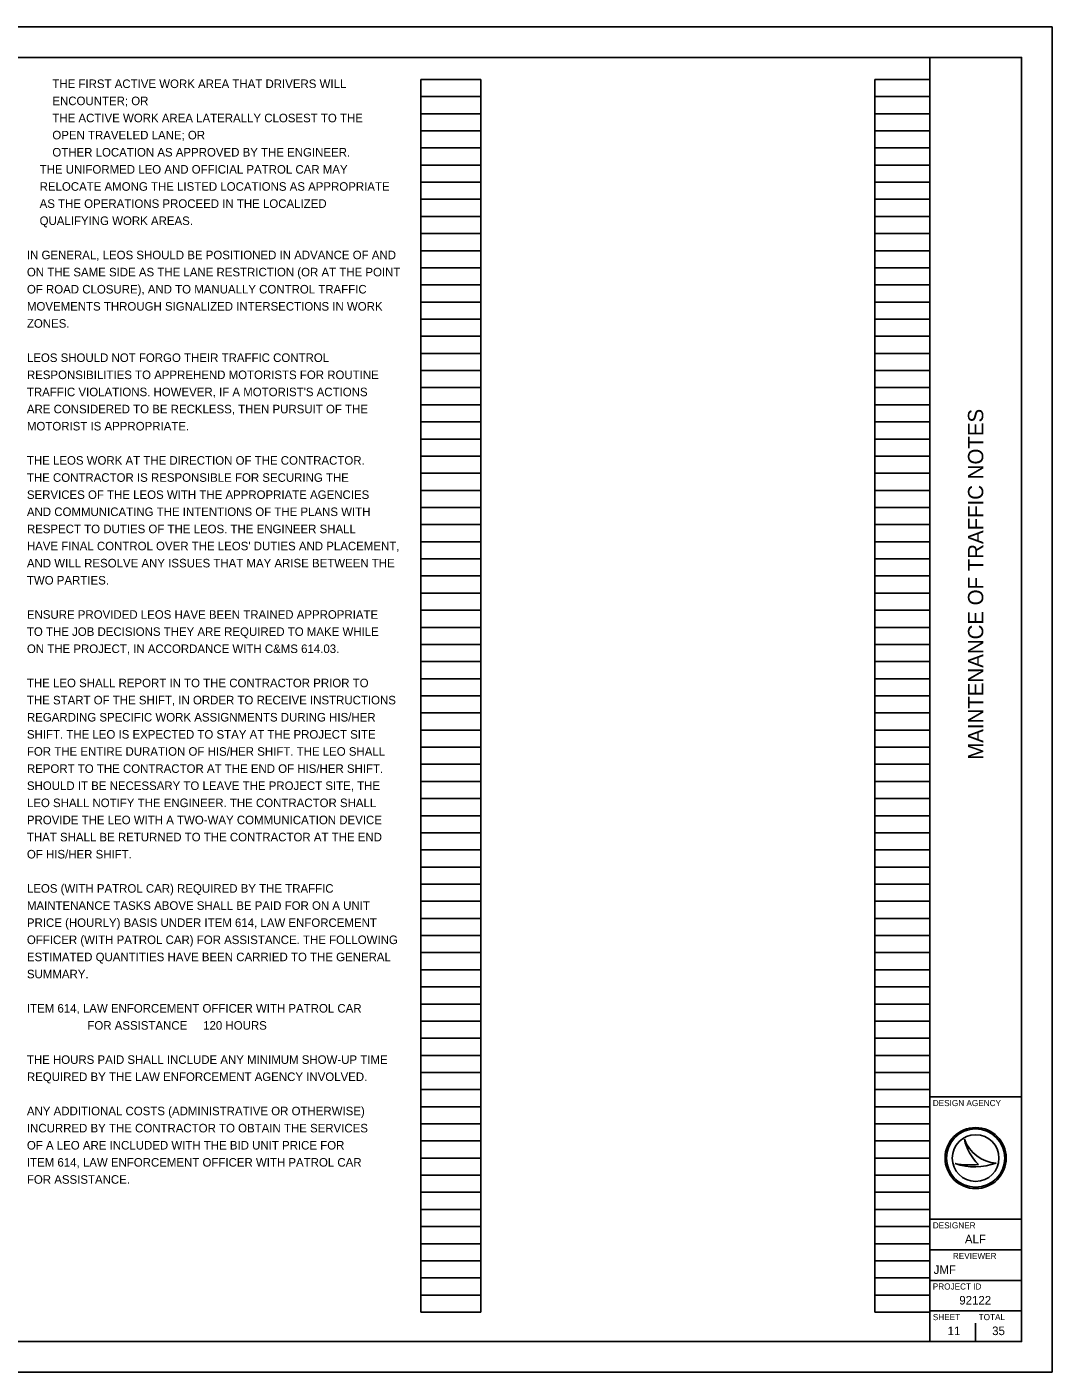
# Model space of a CAD drawing. Extents: x 0 to 34, y 0 to 22.
# Drawn here: x 17.24 to 34, y 0 to 22 of the extents above; entities that cross this region are included whole.
import ezdxf

# ---------------------------------------------------------------- set-up
doc = ezdxf.new("R2010")
doc.units = 0
for name, color, linetype in [('SH_Border', 7, 'Continuous'), ('SH_Cut_Line', 7, 'Continuous'), ('SH_Data', 7, 'Continuous'), ('SH_Text', 7, 'Continuous')]:
    doc.layers.add(name, color=color, linetype=linetype)

msp = doc.modelspace()

# ---------------------------------------------------------------- linework, layer by layer
at = {"layer": 'SH_Border'}
for p, q in [((32, 0.5), (32, 21.5)), ((32, 4.5), (33.5, 4.5)), ((32, 2.5), (33.5, 2.5)), ((32, 2), (33.5, 2)), ((32, 1.5), (33.5, 1.5)), ((32, 1), (33.5, 1))]:
    msp.add_line(p, q, dxfattribs=at)
msp.add_lwpolyline([(1.5, 21.5), (33.5, 21.5), (33.5, 0.5), (1.5, 0.5)], close=True, dxfattribs=at)
at = {"layer": 'SH_Cut_Line'}
msp.add_lwpolyline([(0, 0), (34, 0), (34, 22), (0, 22)], close=True, dxfattribs=at)
at = {"layer": 'SH_Data'}
for p, q in [((23.68, 0.98), (23.68, 21.14)), ((23.68, 21.14), (24.66, 21.14)), ((24.66, 0.98), (24.66, 21.14)), ((31.1, 0.98), (31.1, 21.14)), ((31.1, 21.14), (32, 21.14)), ((32, 0.98), (32, 21.14)), ((23.68, 20.86), (24.66, 20.86)), ((31.1, 20.86), (32, 20.86)), ((23.68, 20.58), (24.66, 20.58)), ((31.1, 20.58), (32, 20.58)), ((23.68, 20.3), (24.66, 20.3)), ((31.1, 20.3), (32, 20.3)), ((23.68, 20.02), (24.66, 20.02)), ((31.1, 20.02), (32, 20.02)), ((23.68, 19.74), (24.66, 19.74)), ((31.1, 19.74), (32, 19.74)), ((23.68, 19.46), (24.66, 19.46)), ((31.1, 19.46), (32, 19.46)), ((23.68, 19.18), (24.66, 19.18)), ((31.1, 19.18), (32, 19.18)), ((23.68, 18.9), (24.66, 18.9)), ((31.1, 18.9), (32, 18.9)), ((23.68, 18.62), (24.66, 18.62)), ((31.1, 18.62), (32, 18.62)), ((23.68, 18.34), (24.66, 18.34)), ((31.1, 18.34), (32, 18.34)), ((23.68, 18.06), (24.66, 18.06)), ((31.1, 18.06), (32, 18.06)), ((23.68, 17.78), (24.66, 17.78)), ((31.1, 17.78), (32, 17.78)), ((23.68, 17.5), (24.66, 17.5)), ((31.1, 17.5), (32, 17.5)), ((23.68, 17.22), (24.66, 17.22)), ((31.1, 17.22), (32, 17.22)), ((23.68, 16.94), (24.66, 16.94)), ((31.1, 16.94), (32, 16.94)), ((23.68, 16.66), (24.66, 16.66)), ((31.1, 16.66), (32, 16.66)), ((23.68, 16.38), (24.66, 16.38)), ((31.1, 16.38), (32, 16.38)), ((23.68, 16.1), (24.66, 16.1)), ((31.1, 16.1), (32, 16.1)), ((23.68, 15.82), (24.66, 15.82)), ((31.1, 15.82), (32, 15.82)), ((23.68, 15.54), (24.66, 15.54)), ((31.1, 15.54), (32, 15.54)), ((23.68, 15.26), (24.66, 15.26)), ((31.1, 15.26), (32, 15.26)), ((23.68, 14.98), (24.66, 14.98)), ((31.1, 14.98), (32, 14.98)), ((23.68, 14.7), (24.66, 14.7)), ((31.1, 14.7), (32, 14.7)), ((23.68, 14.42), (24.66, 14.42)), ((31.1, 14.42), (32, 14.42)), ((23.68, 14.14), (24.66, 14.14)), ((31.1, 14.14), (32, 14.14)), ((23.68, 13.86), (24.66, 13.86)), ((31.1, 13.86), (32, 13.86)), ((23.68, 13.58), (24.66, 13.58)), ((31.1, 13.58), (32, 13.58)), ((23.68, 13.3), (24.66, 13.3)), ((31.1, 13.3), (32, 13.3)), ((23.68, 13.02), (24.66, 13.02)), ((31.1, 13.02), (32, 13.02)), ((23.68, 12.74), (24.66, 12.74)), ((31.1, 12.74), (32, 12.74)), ((23.68, 12.46), (24.66, 12.46)), ((31.1, 12.46), (32, 12.46)), ((23.68, 12.18), (24.66, 12.18)), ((31.1, 12.18), (32, 12.18)), ((23.68, 11.9), (24.66, 11.9)), ((31.1, 11.9), (32, 11.9)), ((23.68, 11.62), (24.66, 11.62)), ((31.1, 11.62), (32, 11.62)), ((23.68, 11.34), (24.66, 11.34)), ((31.1, 11.34), (32, 11.34)), ((23.68, 11.06), (24.66, 11.06)), ((31.1, 11.06), (32, 11.06)), ((23.68, 10.78), (24.66, 10.78)), ((31.1, 10.78), (32, 10.78)), ((23.68, 10.5), (24.66, 10.5)), ((31.1, 10.5), (32, 10.5)), ((23.68, 10.22), (24.66, 10.22)), ((31.1, 10.22), (32, 10.22)), ((23.68, 9.94), (24.66, 9.94)), ((31.1, 9.94), (32, 9.94)), ((23.68, 9.66), (24.66, 9.66)), ((31.1, 9.66), (32, 9.66)), ((23.68, 9.38), (24.66, 9.38)), ((31.1, 9.38), (32, 9.38)), ((23.68, 9.1), (24.66, 9.1)), ((31.1, 9.1), (32, 9.1)), ((23.68, 8.82), (24.66, 8.82)), ((31.1, 8.82), (32, 8.82)), ((23.68, 8.54), (24.66, 8.54)), ((31.1, 8.54), (32, 8.54)), ((23.68, 8.26), (24.66, 8.26)), ((31.1, 8.26), (32, 8.26)), ((23.68, 7.98), (24.66, 7.98)), ((31.1, 7.98), (32, 7.98)), ((23.68, 7.7), (24.66, 7.7)), ((31.1, 7.7), (32, 7.7)), ((23.68, 7.42), (24.66, 7.42)), ((31.1, 7.42), (32, 7.42)), ((23.68, 7.14), (24.66, 7.14)), ((31.1, 7.14), (32, 7.14)), ((23.68, 6.86), (24.66, 6.86)), ((31.1, 6.86), (32, 6.86)), ((23.68, 6.58), (24.66, 6.58)), ((31.1, 6.58), (32, 6.58)), ((23.68, 6.3), (24.66, 6.3)), ((31.1, 6.3), (32, 6.3)), ((23.68, 6.02), (24.66, 6.02)), ((31.1, 6.02), (32, 6.02)), ((23.68, 5.74), (24.66, 5.74)), ((31.1, 5.74), (32, 5.74)), ((23.68, 5.46), (24.66, 5.46)), ((31.1, 5.46), (32, 5.46)), ((23.68, 5.18), (24.66, 5.18)), ((31.1, 5.18), (32, 5.18)), ((23.68, 4.9), (24.66, 4.9)), ((31.1, 4.9), (32, 4.9)), ((23.68, 4.62), (24.66, 4.62)), ((31.1, 4.62), (32, 4.62)), ((23.68, 4.34), (24.66, 4.34)), ((31.1, 4.34), (32, 4.34)), ((23.68, 4.06), (24.66, 4.06)), ((31.1, 4.06), (32, 4.06)), ((23.68, 3.78), (24.66, 3.78)), ((31.1, 3.78), (32, 3.78)), ((32.567, 3.81), (32.567, 3.81)), ((23.68, 3.5), (24.66, 3.5)), ((31.1, 3.5), (32, 3.5)), ((32.417, 3.41), (32.417, 3.41)), ((32.75, 3.5), (32.75, 3.5)), ((33.087, 3.419), (33.087, 3.419)), ((23.68, 3.22), (24.66, 3.22)), ((31.1, 3.22), (32, 3.22)), ((23.68, 2.94), (24.66, 2.94)), ((31.1, 2.94), (32, 2.94)), ((23.68, 2.66), (24.66, 2.66)), ((31.1, 2.66), (32, 2.66)), ((23.68, 2.38), (24.66, 2.38)), ((31.1, 2.38), (32, 2.38)), ((23.68, 2.1), (24.66, 2.1)), ((31.1, 2.1), (32, 2.1)), ((23.68, 1.82), (24.66, 1.82)), ((31.1, 1.82), (32, 1.82)), ((23.68, 1.54), (24.66, 1.54)), ((31.1, 1.54), (32, 1.54)), ((23.68, 1.26), (24.66, 1.26)), ((31.1, 1.26), (32, 1.26)), ((23.68, 0.98), (24.66, 0.98)), ((31.1, 0.98), (32, 0.98)), ((32.375, 0.675), (32.375, 0.675)), ((32.75, 0.5), (32.75, 0.8))]:
    msp.add_line(p, q, dxfattribs=at)
for radius in [0.5, 0.477, 0.477, 0.382]:
    msp.add_circle((32.75, 3.5), radius, dxfattribs=at)
for centre, radius, start, end in [((33.116, 3.998), 0.58, 198.9257, 198.9319), ((33.347, 3.97), 0.796, 191.6379, 191.6421), ((33.116, 3.998), 0.58, 198.9319, 267.1657), ((33.347, 3.97), 0.796, 191.6421, 226.0947), ((32.739, 4.37), 1.013, 251.4576, 290.0832), ((32.648, 4.654), 1.266, 259.4964, 259.4995), ((32.739, 4.37), 1.013, 251.4527, 251.4576), ((32.648, 4.654), 1.266, 259.4995, 276.6672)]:
    msp.add_arc(centre, radius, start, end, dxfattribs=at)

# ---------------------------------------------------------------- texts
msp.add_text('MAINTENANCE OF TRAFFIC NOTES', height=0.25, rotation=90, dxfattribs=at).set_placement((32.875, 10.014))
for s, height, p in [('DESIGN AGENCY', 0.1, (32.05, 4.35)), ('DESIGNER', 0.1, (32.05, 2.35)), ('ALF', 0.14, (32.575, 2.105)), ('REVIEWER', 0.1, (32.378, 1.85)), ('JMF', 0.14, (32.064, 1.605)), ('PROJECT ID', 0.1, (32.05, 1.35)), ('92122', 0.14, (32.483, 1.105)), ('SHEET', 0.1, (32.05, 0.85)), ('TOTAL', 0.1, (32.8, 0.85)), ('11', 0.14, (32.292, 0.605)), ('35', 0.14, (33.02, 0.605))]:
    msp.add_text(s, height=height, dxfattribs=at).set_placement(p)
at = {"layer": 'SH_Text'}
for s, p in [('        THE FIRST ACTIVE WORK AREA THAT DRIVERS WILL', (17.24, 21)), ('        ENCOUNTER; OR', (17.24, 20.72)), ('        THE ACTIVE WORK AREA LATERALLY CLOSEST TO THE', (17.24, 20.44)), ('        OPEN TRAVELED LANE; OR', (17.24, 20.16)), ('        OTHER LOCATION AS APPROVED BY THE ENGINEER.', (17.24, 19.88)), ('    THE UNIFORMED LEO AND OFFICIAL PATROL CAR MAY', (17.24, 19.6)), ('    RELOCATE AMONG THE LISTED LOCATIONS AS APPROPRIATE', (17.24, 19.32)), ('    AS THE OPERATIONS PROCEED IN THE LOCALIZED', (17.24, 19.04)), ('    QUALIFYING WORK AREAS.', (17.24, 18.76)), ('IN GENERAL, LEOS SHOULD BE POSITIONED IN ADVANCE OF AND', (17.24, 18.2)), ('ON THE SAME SIDE AS THE LANE RESTRICTION (OR AT THE POINT', (17.24, 17.92)), ('OF ROAD CLOSURE), AND TO MANUALLY CONTROL TRAFFIC', (17.24, 17.64)), ('MOVEMENTS THROUGH SIGNALIZED INTERSECTIONS IN WORK', (17.24, 17.36)), ('ZONES.', (17.24, 17.08)), ('LEOS SHOULD NOT FORGO THEIR TRAFFIC CONTROL', (17.24, 16.52)), ('RESPONSIBILITIES TO APPREHEND MOTORISTS FOR ROUTINE', (17.24, 16.24)), ("TRAFFIC VIOLATIONS. HOWEVER, IF A MOTORIST'S ACTIONS", (17.24, 15.96)), ('ARE CONSIDERED TO BE RECKLESS, THEN PURSUIT OF THE', (17.24, 15.68)), ('MOTORIST IS APPROPRIATE.', (17.24, 15.4)), ('THE LEOS WORK AT THE DIRECTION OF THE CONTRACTOR.', (17.24, 14.84)), ('THE CONTRACTOR IS RESPONSIBLE FOR SECURING THE', (17.24, 14.56)), ('SERVICES OF THE LEOS WITH THE APPROPRIATE AGENCIES', (17.24, 14.28)), ('AND COMMUNICATING THE INTENTIONS OF THE PLANS WITH', (17.24, 14)), ('RESPECT TO DUTIES OF THE LEOS. THE ENGINEER SHALL', (17.24, 13.72)), ("HAVE FINAL CONTROL OVER THE LEOS' DUTIES AND PLACEMENT,", (17.24, 13.44)), ('AND WILL RESOLVE ANY ISSUES THAT MAY ARISE BETWEEN THE', (17.24, 13.16)), ('TWO PARTIES.', (17.24, 12.88)), ('ENSURE PROVIDED LEOS HAVE BEEN TRAINED APPROPRIATE', (17.24, 12.32)), ('TO THE JOB DECISIONS THEY ARE REQUIRED TO MAKE WHILE', (17.24, 12.04)), ('ON THE PROJECT, IN ACCORDANCE WITH C&MS 614.03.', (17.24, 11.76)), ('THE LEO SHALL REPORT IN TO THE CONTRACTOR PRIOR TO', (17.24, 11.2)), ('THE START OF THE SHIFT, IN ORDER TO RECEIVE INSTRUCTIONS', (17.24, 10.92)), ('REGARDING SPECIFIC WORK ASSIGNMENTS DURING HIS/HER', (17.24, 10.64)), ('SHIFT. THE LEO IS EXPECTED TO STAY AT THE PROJECT SITE', (17.24, 10.36)), ('FOR THE ENTIRE DURATION OF HIS/HER SHIFT. THE LEO SHALL', (17.24, 10.08)), ('REPORT TO THE CONTRACTOR AT THE END OF HIS/HER SHIFT.', (17.24, 9.8)), ('SHOULD IT BE NECESSARY TO LEAVE THE PROJECT SITE, THE', (17.24, 9.52)), ('LEO SHALL NOTIFY THE ENGINEER. THE CONTRACTOR SHALL', (17.24, 9.24)), ('PROVIDE THE LEO WITH A TWO-WAY COMMUNICATION DEVICE', (17.24, 8.96)), ('THAT SHALL BE RETURNED TO THE CONTRACTOR AT THE END', (17.24, 8.68)), ('OF HIS/HER SHIFT.', (17.24, 8.4)), ('LEOS (WITH PATROL CAR) REQUIRED BY THE TRAFFIC', (17.24, 7.84)), ('MAINTENANCE TASKS ABOVE SHALL BE PAID FOR ON A UNIT', (17.24, 7.56)), ('PRICE (HOURLY) BASIS UNDER ITEM 614, LAW ENFORCEMENT', (17.24, 7.28)), ('OFFICER (WITH PATROL CAR) FOR ASSISTANCE. THE FOLLOWING', (17.24, 7)), ('ESTIMATED QUANTITIES HAVE BEEN CARRIED TO THE GENERAL', (17.24, 6.72)), ('SUMMARY.', (17.24, 6.44)), ('ITEM 614, LAW ENFORCEMENT OFFICER WITH PATROL CAR', (17.24, 5.88)), ('                   FOR ASSISTANCE     120 HOURS', (17.24, 5.6)), ('THE HOURS PAID SHALL INCLUDE ANY MINIMUM SHOW-UP TIME', (17.24, 5.04)), ('REQUIRED BY THE LAW ENFORCEMENT AGENCY INVOLVED.', (17.24, 4.76)), ('ANY ADDITIONAL COSTS (ADMINISTRATIVE OR OTHERWISE)', (17.24, 4.2)), ('INCURRED BY THE CONTRACTOR TO OBTAIN THE SERVICES', (17.24, 3.92)), ('OF A LEO ARE INCLUDED WITH THE BID UNIT PRICE FOR', (17.24, 3.64)), ('ITEM 614, LAW ENFORCEMENT OFFICER WITH PATROL CAR', (17.24, 3.36)), ('FOR ASSISTANCE.', (17.24, 3.08))]:
    msp.add_text(s, height=0.14, dxfattribs=at).set_placement(p)

doc.saveas('drawing.dxf')
